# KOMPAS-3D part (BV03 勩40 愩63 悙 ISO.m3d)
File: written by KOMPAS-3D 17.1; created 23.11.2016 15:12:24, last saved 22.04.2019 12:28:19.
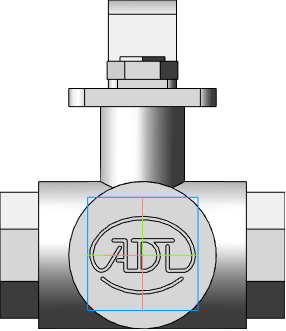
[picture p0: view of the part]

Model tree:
1. Операция без истории:2  (labels: Сталь 20  ГОСТ 1050-88)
